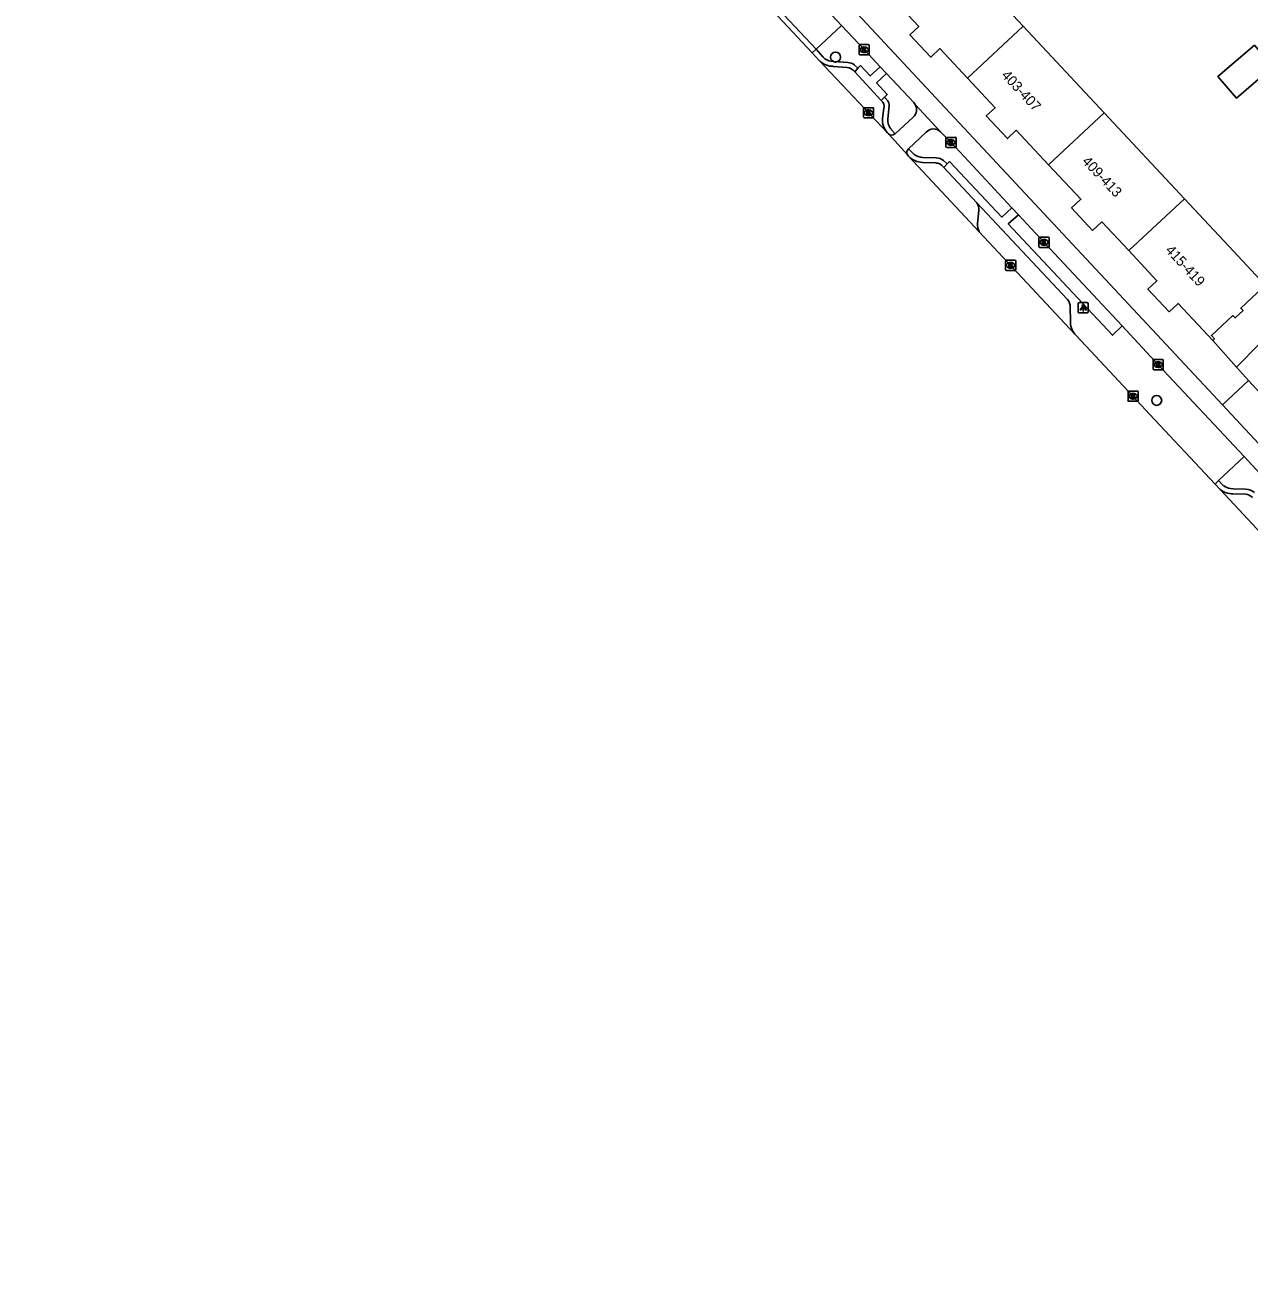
# Model space of a CAD drawing. Extents: x 163150 to 163546, y 380933 to 381635.
# Drawn here: x 163188.4 to 163309.2, y 380985.6 to 381108.1 of the extents above; entities that cross this region are included whole.
import ezdxf

# ---------------------------------------------------------------- set-up
doc = ezdxf.new("R2010")
doc.units = 0
for name, color, linetype in [('IMGEO_Berm_open', 7, 'Continuous'), ('IMGEO_Boom', 7, 'Continuous'), ('IMGEO_Fietspad_gesloten', 7, 'Continuous'), ('IMGEO_Kolk', 7, 'Continuous'), ('IMGEO_Lichtpunt', 7, 'Continuous'), ('IMGEO_Pand', 7, 'Continuous'), ('IMGEO_Pand_nummerreeks', 7, 'Continuous'), ('IMGEO_Parkeervlak_open', 7, 'Continuous'), ('IMGEO_Rijbaan_lokaal_gesloten', 7, 'Continuous'), ('IMGEO_Rijbaan_lokaal_open', 7, 'Continuous'), ('IMGEO_Voetpad_open', 7, 'Continuous')]:
    doc.layers.add(name, color=color, linetype=linetype)

msp = doc.modelspace()

# ---------------------------------------------------------------- linework, layer by layer
at = {"layer": 'IMGEO_Berm_open'}
for points in [[(163267.17, 381104.89), (163266.46, 381105.68)], [(163269.59, 381104.37), (163268.2, 381104.49), (163267.93, 381104.51)], [(163270.6, 381103.8), (163270.24, 381104.15)], [(163273.56, 381100.59), (163273.21, 381100.95)], [(163273.53, 381098.82), (163273.64, 381099.78), (163273.68, 381100.12)], [(163274.26, 381097.35), (163273.92, 381097.73)], [(163276.12, 381095.34), (163275.6, 381095.87)], [(163278.32, 381094.97), (163277.01, 381095.02)], [(163279.41, 381094.38), (163279.05, 381094.72)], [(163306.18, 381063.14), (163306.64, 381062.65)], [(163307.33, 381062.35), (163307.61, 381062.33), (163308.84, 381062.3)]]:
    msp.add_lwpolyline(points, dxfattribs=at)
for centre, radius, start, end in [((163268.14, 381105.89), 1.4, 225.7956, 261.3145), ((163269.48, 381102.94), 1.43, 57.5894, 85.593), ((163272.42, 381100.05), 1.26, 3.177, 25.0693), ((163274.91, 381098.7), 1.38, 174.9699, 224.5238), ((163277.07, 381096.58), 1.56, 232.6026, 267.8452), ((163278.25, 381093.54), 1.43, 56.0145, 86.973), ((163307.6, 381063.92), 1.59, 233.0586, 260.364), ((163308.79, 381060.82), 1.48, 50.8561, 87.9177)]:
    msp.add_arc(centre, radius, start, end, dxfattribs=at)
at = {"layer": 'IMGEO_Boom'}
for centre in [(163268.39, 381104.91), (163300.07, 381071.05)]:
    msp.add_circle(centre, 0.489, dxfattribs=at)
at = {"layer": 'IMGEO_Fietspad_gesloten'}
for points in [[(163306.56, 381070.61), (163278.28, 381100.89), (163188.42, 381197.24)], [(163268.98, 381108.03), (163271.24, 381105.61), (163272.8, 381103.94)], [(163272.8, 381103.94), (163273.41, 381103.29)], [(163273.41, 381103.29), (163276.11, 381100.43), (163276.25, 381100.24)], [(163276.25, 381100.24), (163278.75, 381097.54)], [(163278.75, 381097.54), (163279.79, 381096.48), (163285.78, 381090.04)], [(163285.78, 381090.04), (163286.43, 381089.35)], [(163286.43, 381089.35), (163289, 381086.59), (163296.65, 381078.4)], [(163296.65, 381078.4), (163300.25, 381074.54), (163308.69, 381065.5)], [(163386.17, 380985.56), (163372.65, 381000), (163319.83, 381056.4), (163310.14, 381066.77), (163306.56, 381070.61)], [(163308.69, 381065.5), (163311.9, 381062.06)]]:
    msp.add_lwpolyline(points, dxfattribs=at)
at = {"layer": 'IMGEO_Kolk'}
for p, q in [((163270.71, 381105.21), (163270.71, 381106.06)), ((163270.78, 381106.14), (163271.64, 381106.14)), ((163271.2, 381105.91), (163271.22, 381105.91)), ((163271.71, 381106.06), (163271.71, 381105.21)), ((163271.64, 381105.13), (163270.78, 381105.13)), ((163271.22, 381105.36), (163271.2, 381105.36)), ((163271.14, 381099), (163271.14, 381099.85)), ((163271.22, 381099.92), (163272.07, 381099.92)), ((163272.14, 381099.85), (163272.14, 381099)), ((163272.07, 381098.92), (163271.22, 381098.92)), ((163271.63, 381099.7), (163271.66, 381099.7)), ((163271.65, 381099.14), (163271.63, 381099.14)), ((163279.28, 381096.07), (163279.28, 381096.92)), ((163279.35, 381096.99), (163280.2, 381096.99)), ((163279.76, 381096.77), (163279.79, 381096.77)), ((163279.79, 381096.21), (163279.76, 381096.21)), ((163280.28, 381096.92), (163280.28, 381096.07)), ((163280.2, 381095.99), (163279.35, 381095.99)), ((163288.45, 381086.21), (163288.45, 381087.07)), ((163288.53, 381087.14), (163289.38, 381087.14)), ((163288.94, 381086.92), (163288.96, 381086.92)), ((163288.96, 381086.36), (163288.94, 381086.36)), ((163289.45, 381087.07), (163289.45, 381086.21)), ((163289.38, 381086.14), (163288.53, 381086.14)), ((163285.16, 381083.94), (163285.16, 381084.79)), ((163285.23, 381084.87), (163286.08, 381084.87)), ((163286.08, 381083.87), (163285.23, 381083.87)), ((163285.67, 381084.09), (163285.64, 381084.09)), ((163285.65, 381084.65), (163285.67, 381084.65)), ((163286.16, 381084.79), (163286.16, 381083.94)), ((163299.71, 381074.16), (163299.71, 381075.01)), ((163299.79, 381075.08), (163300.64, 381075.08)), ((163300.64, 381074.08), (163299.79, 381074.08)), ((163300.2, 381074.86), (163300.22, 381074.86)), ((163300.22, 381074.3), (163300.2, 381074.3)), ((163300.71, 381075.01), (163300.71, 381074.16)), ((163297.24, 381071.03), (163297.24, 381071.89)), ((163297.31, 381071.96), (163298.16, 381071.96)), ((163297.72, 381071.74), (163297.75, 381071.74)), ((163298.24, 381071.89), (163298.24, 381071.03)), ((163298.16, 381070.96), (163297.31, 381070.96)), ((163297.75, 381071.18), (163297.72, 381071.18))]:
    msp.add_line(p, q, dxfattribs=at)
for points in [[(163270.71, 381105.21), (163270.71, 381106.06)], [(163270.78, 381106.14), (163271.64, 381106.14)], [(163271.71, 381106.06), (163271.71, 381105.21)], [(163271.64, 381105.13), (163270.78, 381105.13)], [(163271.03, 381105.83), (163271.15, 381105.83), (163271.15, 381105.68), (163271.28, 381105.83), (163271.45, 381105.83), (163271.3, 381105.68), (163271.45, 381105.43), (163271.3, 381105.43), (163271.22, 381105.6), (163271.15, 381105.53), (163271.15, 381105.43), (163271.03, 381105.43), (163271.03, 381105.83)], [(163271.14, 381099), (163271.14, 381099.85)], [(163271.22, 381099.92), (163272.07, 381099.92)], [(163272.14, 381099.85), (163272.14, 381099)], [(163272.07, 381098.92), (163271.22, 381098.92)], [(163271.46, 381099.62), (163271.59, 381099.62), (163271.59, 381099.47), (163271.72, 381099.62), (163271.88, 381099.62), (163271.74, 381099.47), (163271.89, 381099.22), (163271.74, 381099.22), (163271.65, 381099.39), (163271.59, 381099.32), (163271.59, 381099.22), (163271.46, 381099.22), (163271.46, 381099.62)], [(163279.28, 381096.07), (163279.28, 381096.92)], [(163279.35, 381096.99), (163280.2, 381096.99)], [(163279.6, 381096.69), (163279.72, 381096.69), (163279.72, 381096.54), (163279.85, 381096.69), (163280.01, 381096.69), (163279.87, 381096.54), (163280.02, 381096.29), (163279.87, 381096.29), (163279.78, 381096.46), (163279.72, 381096.39), (163279.72, 381096.29), (163279.6, 381096.29), (163279.6, 381096.69)], [(163280.28, 381096.92), (163280.28, 381096.07)], [(163280.2, 381095.99), (163279.35, 381095.99)], [(163288.45, 381086.21), (163288.45, 381087.07)], [(163288.53, 381087.14), (163289.38, 381087.14)], [(163288.77, 381086.84), (163288.9, 381086.84), (163288.9, 381086.69), (163289.02, 381086.84), (163289.19, 381086.84), (163289.04, 381086.69), (163289.2, 381086.44), (163289.04, 381086.44), (163288.96, 381086.61), (163288.9, 381086.54), (163288.9, 381086.44), (163288.77, 381086.44), (163288.77, 381086.84)], [(163289.45, 381087.07), (163289.45, 381086.21)], [(163289.38, 381086.14), (163288.53, 381086.14)], [(163285.16, 381083.94), (163285.16, 381084.79)], [(163285.23, 381084.87), (163286.08, 381084.87)], [(163286.08, 381083.87), (163285.23, 381083.87)], [(163285.48, 381084.57), (163285.6, 381084.57), (163285.6, 381084.42), (163285.73, 381084.57), (163285.9, 381084.57), (163285.75, 381084.42), (163285.9, 381084.17), (163285.75, 381084.17), (163285.67, 381084.33), (163285.6, 381084.26), (163285.6, 381084.17), (163285.48, 381084.17), (163285.48, 381084.57)], [(163286.16, 381084.79), (163286.16, 381083.94)], [(163299.71, 381074.16), (163299.71, 381075.01)], [(163299.79, 381075.08), (163300.64, 381075.08)], [(163300.64, 381074.08), (163299.79, 381074.08)], [(163300.03, 381074.78), (163300.16, 381074.78), (163300.16, 381074.63), (163300.28, 381074.78), (163300.45, 381074.78), (163300.3, 381074.63), (163300.46, 381074.38), (163300.3, 381074.38), (163300.22, 381074.55), (163300.16, 381074.48), (163300.16, 381074.38), (163300.03, 381074.38), (163300.03, 381074.78)], [(163300.71, 381075.01), (163300.71, 381074.16)], [(163297.24, 381071.03), (163297.24, 381071.89)], [(163297.31, 381071.96), (163298.16, 381071.96)], [(163297.56, 381071.66), (163297.68, 381071.66), (163297.68, 381071.51), (163297.81, 381071.66), (163297.97, 381071.66), (163297.83, 381071.51), (163297.98, 381071.26), (163297.83, 381071.26), (163297.74, 381071.43), (163297.68, 381071.36), (163297.68, 381071.26), (163297.56, 381071.26), (163297.56, 381071.66)], [(163298.24, 381071.89), (163298.24, 381071.03)], [(163298.16, 381070.96), (163297.31, 381070.96)]]:
    msp.add_lwpolyline(points, dxfattribs=at)
for centre, start, end in [((163270.79, 381106.06), 91.552, 178.448), ((163270.79, 381106.06), 91.552, 178.448), ((163271.63, 381106.06), 1.552, 88.448), ((163271.63, 381106.06), 1.552, 88.448), ((163270.79, 381105.21), 181.552, 268.448), ((163270.79, 381105.21), 181.552, 268.448), ((163271.63, 381105.21), 271.552, 358.448), ((163271.63, 381105.21), 271.552, 358.448), ((163271.22, 381099.85), 91.552, 178.448), ((163271.22, 381099.85), 91.552, 178.448), ((163272.07, 381099.85), 1.552, 88.448), ((163272.07, 381099.85), 1.552, 88.448), ((163271.22, 381099), 181.552, 268.448), ((163271.22, 381099), 181.552, 268.448), ((163272.07, 381099), 271.552, 358.448), ((163272.07, 381099), 271.552, 358.448), ((163279.35, 381096.92), 91.552, 178.448), ((163279.35, 381096.92), 91.552, 178.448), ((163279.35, 381096.07), 181.552, 268.448), ((163279.35, 381096.07), 181.552, 268.448), ((163280.2, 381096.92), 1.552, 88.448), ((163280.2, 381096.92), 1.552, 88.448), ((163280.2, 381096.07), 271.552, 358.448), ((163280.2, 381096.07), 271.552, 358.448), ((163288.53, 381087.07), 91.552, 178.448), ((163288.53, 381087.07), 91.552, 178.448), ((163289.38, 381087.07), 1.552, 88.448), ((163289.38, 381087.07), 1.552, 88.448), ((163288.53, 381086.22), 181.552, 268.448), ((163288.53, 381086.22), 181.552, 268.448), ((163289.38, 381086.22), 271.552, 358.448), ((163289.38, 381086.22), 271.552, 358.448), ((163285.23, 381084.79), 91.552, 178.448), ((163285.23, 381084.79), 91.552, 178.448), ((163285.23, 381083.94), 181.552, 268.448), ((163285.23, 381083.94), 181.552, 268.448), ((163286.08, 381084.79), 1.552, 88.448), ((163286.08, 381084.79), 1.552, 88.448), ((163286.08, 381083.94), 271.552, 358.448), ((163286.08, 381083.94), 271.552, 358.448), ((163299.79, 381075.01), 91.552, 178.448), ((163299.79, 381075.01), 91.552, 178.448), ((163299.79, 381074.16), 181.552, 268.448), ((163299.79, 381074.16), 181.552, 268.448), ((163300.64, 381075.01), 1.552, 88.448), ((163300.64, 381075.01), 1.552, 88.448), ((163300.64, 381074.16), 271.552, 358.448), ((163300.64, 381074.16), 271.552, 358.448), ((163297.31, 381071.89), 91.552, 178.448), ((163297.31, 381071.89), 91.552, 178.448), ((163298.16, 381071.89), 1.552, 88.448), ((163298.16, 381071.89), 1.552, 88.448), ((163297.31, 381071.04), 181.552, 268.448), ((163297.31, 381071.04), 181.552, 268.448), ((163298.16, 381071.04), 271.552, 358.448), ((163298.16, 381071.04), 271.552, 358.448)]:
    msp.add_arc(centre, 0.0765, start, end, dxfattribs=at)
for centre, major_axis, ratio, start_param, end_param in [((163271.2, 381105.63), (-0.387, 0.002), 0.722429, 4.712389, 7.853982), ((163271.22, 381105.63), (-0.39, 0.002), 0.717154, 1.570796, 4.712389), ((163271.63, 381099.42), (-0.387, 0.002), 0.722429, 4.712389, 7.853982), ((163271.65, 381099.42), (-0.39, 0.002), 0.717154, 1.570796, 4.712389), ((163279.76, 381096.49), (-0.387, 0.002), 0.722429, 4.712389, 7.853982), ((163279.79, 381096.49), (-0.39, 0.002), 0.717154, 1.570796, 4.712389), ((163288.94, 381086.64), (-0.387, 0.002), 0.722429, 4.712389, 7.853982), ((163288.96, 381086.64), (-0.39, 0.002), 0.717154, 1.570796, 4.712389), ((163285.64, 381084.37), (-0.387, 0.002), 0.722429, 4.712389, 7.853982), ((163285.67, 381084.37), (-0.39, 0.002), 0.717154, 1.570796, 4.712389), ((163300.2, 381074.58), (-0.387, 0.002), 0.722429, 4.712389, 7.853982), ((163300.22, 381074.58), (-0.39, 0.002), 0.717154, 1.570796, 4.712389), ((163297.72, 381071.46), (-0.387, 0.002), 0.722429, 4.712389, 7.853982), ((163297.75, 381071.46), (-0.39, 0.002), 0.717154, 1.570796, 4.712389)]:
    msp.add_ellipse(centre, major_axis=major_axis, ratio=ratio, start_param=start_param, end_param=end_param, dxfattribs=at)
at = {"layer": 'IMGEO_Lichtpunt'}
for p, q in [((163292.32, 381080.59), (163292.32, 381079.78)), ((163292.32, 381080.59), (163292.32, 381079.78)), ((163293.22, 381080.69), (163292.42, 381080.69)), ((163293.22, 381080.69), (163292.42, 381080.69)), ((163293.32, 381079.78), (163293.32, 381080.59)), ((163293.32, 381079.78), (163293.32, 381080.59)), ((163292.42, 381079.69), (163293.22, 381079.69)), ((163292.42, 381079.69), (163293.22, 381079.69))]:
    msp.add_line(p, q, dxfattribs=at)
for points in [[(163292.7, 381080.25), (163292.74, 381080.23), (163292.55, 381079.96), (163292.51, 381079.99), (163292.7, 381080.25)], [(163292.8, 381080.21), (163292.85, 381080.21), (163292.85, 381079.88), (163292.8, 381079.88), (163292.8, 381080.21)], [(163292.91, 381080.23), (163292.95, 381080.25), (163293.13, 381079.99), (163293.1, 381079.96), (163292.91, 381080.23)]]:
    msp.add_lwpolyline(points, dxfattribs=at)
msp.add_circle((163292.82, 381080.39), 0.0994, dxfattribs=at)
for centre, start, end in [((163292.42, 381080.59), 90, 180), ((163292.42, 381080.59), 90, 180), ((163293.22, 381080.59), 0, 90), ((163293.22, 381080.59), 0, 90), ((163292.42, 381079.78), 180, 270), ((163292.42, 381079.78), 180, 270), ((163293.22, 381079.78), 270, 0), ((163293.22, 381079.78), 270, 360)]:
    msp.add_arc(centre, 0.0946, start, end, dxfattribs=at)
at = {"layer": 'IMGEO_Pand'}
for points in [[(163278.3, 381116.88), (163278.43, 381117), (163281.85, 381113.35), (163286.89, 381107.95)], [(163281.41, 381102.83), (163278.68, 381105.74), (163277.79, 381104.91), (163275.72, 381107.12), (163276.6, 381107.94), (163272.86, 381111.94)], [(163286.89, 381107.95), (163281.41, 381102.83)], [(163286.89, 381107.95), (163294.88, 381099.41)], [(163309.7, 381106.08), (163306.1, 381103.01), (163307.93, 381100.87), (163311.52, 381103.94), (163309.7, 381106.08)], [(163281.41, 381102.83), (163284.13, 381099.91), (163283.26, 381099.1), (163285.34, 381096.87), (163286.22, 381097.69), (163289.4, 381094.29)], [(163294.88, 381099.41), (163289.4, 381094.29)], [(163294.88, 381099.41), (163302.8, 381090.94)], [(163289.4, 381094.29), (163292.59, 381090.89), (163291.67, 381090.03), (163293.75, 381087.81), (163294.66, 381088.66), (163297.32, 381085.82)], [(163297.32, 381085.82), (163302.8, 381090.94)], [(163302.8, 381090.94), (163307.63, 381085.78), (163310.74, 381082.46)], [(163297.32, 381085.82), (163300.09, 381082.85), (163299.2, 381082.02), (163301.29, 381079.79), (163302.17, 381080.61), (163305.59, 381076.95)], [(163310.74, 381082.46), (163311.05, 381082.13), (163310.81, 381081.9), (163310.55, 381082.18), (163308.36, 381080.14), (163308.59, 381079.9), (163307.82, 381079.18), (163307.59, 381079.42), (163305.46, 381077.44), (163305.77, 381077.11), (163305.59, 381076.95)]]:
    msp.add_lwpolyline(points, dxfattribs=at)
at = {"layer": 'IMGEO_Parkeervlak_open'}
for points in [[(163269.52, 381103.87), (163268.16, 381103.99)], [(163273.03, 381098.85), (163273.14, 381099.86)], [(163278.28, 381094.47), (163276.97, 381094.52)], [(163279.07, 381094.02), (163278.97, 381094.13)], [(163282.39, 381088.49), (163282.52, 381089.79)], [(163308.82, 381061.8), (163307.59, 381061.83)]]:
    msp.add_lwpolyline(points, dxfattribs=at)
for centre, radius, start, end in [((163268.11, 381105.82), 1.82, 224.9707, 271.6913), ((163269.44, 381102.82), 1.06, 37.7029, 85.4505), ((163272.45, 381100.07), 0.725, 342.6083, 51.6587), ((163274.89, 381098.69), 1.87, 175.2128, 221.8289), ((163277.06, 381096.57), 2.06, 223.9105, 267.3698), ((163278.25, 381093.54), 0.923, 39.0617, 88.1423), ((163281.27, 381089.87), 1.25, 356.2827, 32.6808), ((163283.85, 381088.37), 1.46, 175.2014, 208.0698), ((163307.6, 381063.93), 2.1, 232.5057, 269.7604), ((163308.81, 381060.88), 0.918, 39.9868, 89.3564)]:
    msp.add_arc(centre, radius, start, end, dxfattribs=at)
at = {"layer": 'IMGEO_Rijbaan_lokaal_gesloten'}
for points in [[(163266.09, 381105.34), (163259.3, 381112.6)], [(163266.82, 381104.53), (163266.09, 381105.34)], [(163273.5, 381097.45), (163266.82, 381104.53)], [(163273.6, 381097.33), (163273.5, 381097.45)], [(163275.47, 381095.27), (163273.6, 381097.33)], [(163275.58, 381095.15), (163275.47, 381095.27)], [(163282.56, 381087.68), (163275.58, 381095.15)], [(163292, 381077.58), (163282.56, 381087.68)], [(163305.82, 381062.79), (163299.37, 381069.7), (163297.75, 381071.45), (163292.13, 381077.44), (163292, 381077.58)], [(163306.32, 381062.26), (163305.82, 381062.79)], [(163312.96, 381055.18), (163310.91, 381057.37), (163306.32, 381062.26)]]:
    msp.add_lwpolyline(points, dxfattribs=at)
at = {"layer": 'IMGEO_Rijbaan_lokaal_open'}
for points in [[(163262.15, 381115.35), (163268.98, 381108.03)], [(163266.46, 381105.68), (163259.66, 381112.95)], [(163266.46, 381105.68), (163268.98, 381108.03)], [(163307.95, 381074.34), (163325.92, 381092.56), (163328.54, 381095.22), (163335.38, 381102.16)], [(163309.14, 381073.02), (163307.95, 381074.34)], [(163310.34, 381071.71), (163309.14, 381073.02)]]:
    msp.add_lwpolyline(points, dxfattribs=at)
at = {"layer": 'IMGEO_Voetpad_open'}
for points in [[(163266.09, 381105.34), (163266.46, 381105.68)], [(163270.28, 381103.47), (163270.6, 381103.8)], [(163272.9, 381100.64), (163270.28, 381103.47)], [(163270.6, 381103.8), (163270.86, 381104.07), (163271.81, 381103.05), (163272.8, 381103.94)], [(163273.41, 381103.29), (163272.44, 381102.37), (163273.49, 381101.22), (163273.21, 381100.95)], [(163273.21, 381100.95), (163272.9, 381100.64)], [(163274.26, 381097.35), (163276.06, 381098.99)], [(163274.23, 381097.33), (163274.26, 381097.35)], [(163277.34, 381097.49), (163275.6, 381095.87)], [(163275.6, 381095.87), (163275.59, 381095.86)], [(163279.41, 381094.38), (163279.07, 381094.02)], [(163279.07, 381094.02), (163282.33, 381090.55)], [(163285.78, 381090.04), (163284.8, 381089.13), (163279.62, 381094.61), (163279.41, 381094.38)], [(163282.33, 381090.55), (163291.28, 381080.99)], [(163296.65, 381078.4), (163295.7, 381077.47), (163285.42, 381088.45), (163286.43, 381089.35)], [(163291.53, 381080.26), (163291.57, 381078.88)], [(163305.59, 381076.95), (163307.95, 381074.34)], [(163309.14, 381073.02), (163306.56, 381070.61)], [(163306.18, 381063.14), (163308.69, 381065.5)], [(163305.82, 381062.79), (163306.18, 381063.14)]]:
    msp.add_lwpolyline(points, dxfattribs=at)
for centre, radius, start, end in [((163275.36, 381099.74), 1.02, 313.0771, 29.479), ((163273.92, 381097.65), 0.45, 225.3446, 313.7431), ((163278.06, 381096.87), 0.958, 44.6692, 139.3955), ((163275.84, 381095.5), 0.44, 125.1833, 211.1476), ((163290.47, 381080.31), 1.06, 357.1925, 40.0062), ((163293.43, 381078.78), 1.87, 176.8946, 220.1069)]:
    msp.add_arc(centre, radius, start, end, dxfattribs=at)

# ---------------------------------------------------------------- texts
at = {"layer": 'IMGEO_Pand_nummerreeks'}
for s, rotation, p in [('403-407', 312.7688, (163284.69, 381103.06)), ('409-413', 313.4378, (163292.64, 381094.57)), ('415-419', 312.668, (163300.87, 381085.81))]:
    msp.add_text(s, height=1, rotation=rotation, dxfattribs=at).set_placement(p)

doc.saveas('drawing.dxf')
